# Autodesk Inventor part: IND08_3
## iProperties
Created: 2006-01
Part Number: IND08_3
Document SubType Name: Modeling
Designer: DES
Author: DES
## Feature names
1. Extrude Block
2. Spotface Extrude Half [Extrusion]
3. Revolve Cav Form
